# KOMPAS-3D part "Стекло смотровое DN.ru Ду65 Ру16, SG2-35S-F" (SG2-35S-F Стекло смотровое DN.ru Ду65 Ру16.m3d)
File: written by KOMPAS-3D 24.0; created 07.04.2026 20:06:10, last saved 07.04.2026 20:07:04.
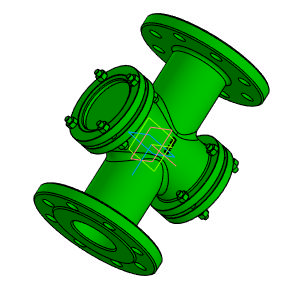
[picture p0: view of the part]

Document properties: Автор: Main; Полное имя файла: D:\DN.ru Аутсерс\Стекло смотровое DN.ru\SG2-35S-F Стекло смотровое DN.ru Ду65 Ру16\SG2-35S-F Стекло смотровое DN.ru Ду65 Ру16.m3d

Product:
- Body: Тело 1  | qty 1
    Масса: 13.01185
- Part/product: Стекло смотровое DN.ru Ду65 Ру16  | designation SG2-35S-F
    Масса: 14
    Раздел спецификации: Прочие изделия
    Примечание: D500-00097

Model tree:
1. Операция без истории:1

Expressions: SG2-35S-F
